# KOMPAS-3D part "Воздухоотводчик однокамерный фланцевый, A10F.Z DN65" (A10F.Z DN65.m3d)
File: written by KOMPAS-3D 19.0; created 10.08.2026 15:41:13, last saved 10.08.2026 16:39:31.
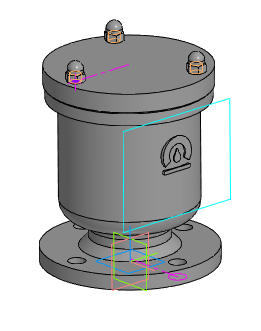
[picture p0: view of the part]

Document properties: Автор: Энергия; Полное имя файла: Z:\3.Личные\kachalov\001_3d для проектировщиков\x.x Тип A10F.Z Воздухоотводчик однокамерный фланцевый\A10F.Z DN65.m3d

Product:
- Part/product: Воздухоотводчик однокамерный фланцевый  | designation A10F.Z DN65
    Масса: 23.1627
  - Body: Тело 1
      Масса: 23.0675
  - Component [standard]: Гайка М12-6H (S18) ГОСТ 11860-85  | qty 3  | Масса: 0.02606; Раздел спецификации: Стандартные изделия; Рассекать на разрезах: no; source file: C:\Program Files\ASCON\KOMPAS-3D v19\Libs\PARTLib\DATA\vault\Methods\Kompas\3D\PLib_Blind_Nut_type1_900.m3d

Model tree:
1. Эскиз:1
2. Элемент вращения:1
     Угол 1 = 360
3. Скругление:1  (with: Элемент вращения:1)
     Радиус = 10
4. Фаска:1  (with: Элемент вращения:1)
     Угол = 45; Длина 1 = 10; Длина 2 = 10
5. Эскиз:2  (with: Элемент вращения:1)
6. Точка:1
     Y = -72.5; Z = 213; Координата Y = -72.5; Координата Z = 213
7. Массив по концентрической сетке:1  (with: Элемент вращения:1)  (3 pattern instances)
     Шаг 2 = 360
8. Эскиз:3  (with: Элемент вращения:1)
9. Элемент выдавливания:1  (with: Элемент вращения:1, Массив по концентрической сетке:1, Эскиз:3)  (4 pattern instances)
     Расстояние 2 = 16; N 1 = 1; Шаг 1 = 10; Шаг 2 = 360; Номер 1 = 1
10. Касательная плоскость:1  (with: Элемент вращения:1)
11. Эскиз:4
12. Элемент выдавливания:2  (with: Элемент вращения:1)  (labels: Фаска наружная:1)
     Расстояние 1 = 1; Ориентация = 2

Expressions: Dn/2; D2/2; D/2; B/2; D1/2; H/2
Referenced files in C:\Program Files\ASCON\KOMPAS-3D v19\Libs\PARTLib\DATA\vault\Methods\Kompas\3D\: PLib_Blind_Nut_type1_900.m3d
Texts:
  A10F.Z DN65
  Гайка М12-6H (S18) ГОСТ 11860-85 (1)
  foc1
  foc2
